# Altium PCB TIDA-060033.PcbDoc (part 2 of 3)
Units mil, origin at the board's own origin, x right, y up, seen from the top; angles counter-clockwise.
Board outline 1900 x 3360 mil, 8 copper layers (Top Layer L1, GND Plane L2, GND Plane L3, GND/Signal L4, GND Plane L5, GND Plane L6, GND Plane L7, Bottom Layer L8), stack 61.4 mil thick; 78 components, 27 nets, 146 pads, 1944 vias.
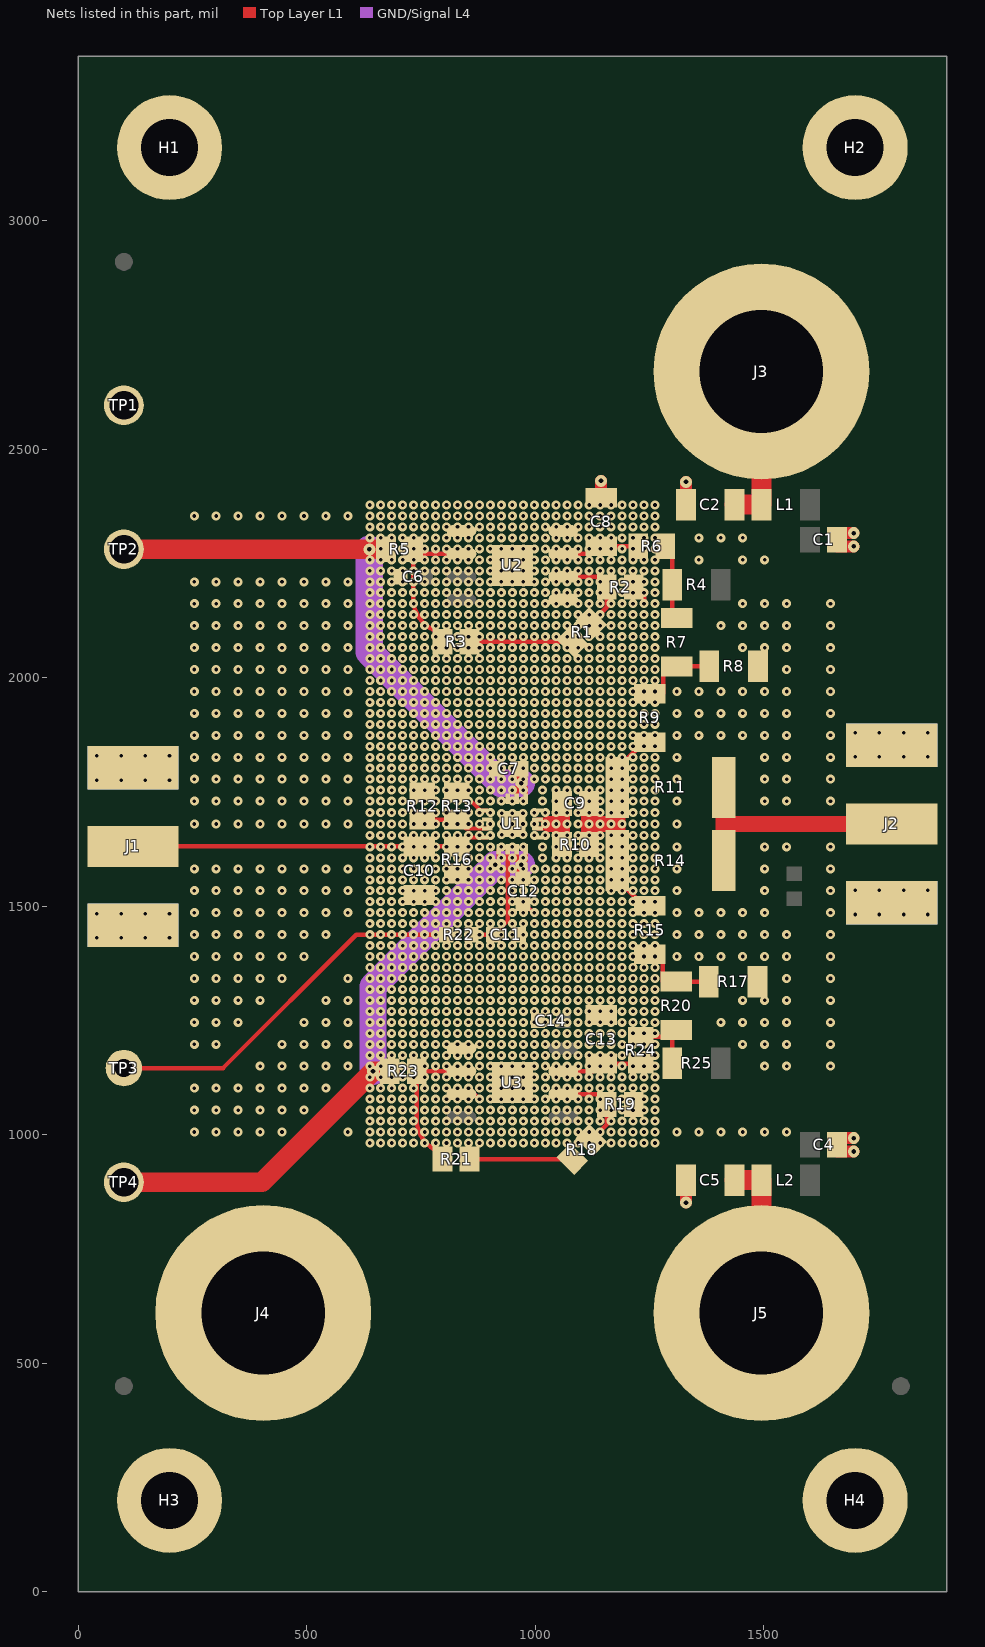
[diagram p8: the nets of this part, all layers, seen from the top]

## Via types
v1: diameter 19.68, hole 7.87, Top Layer L1 to Bottom Layer L8, tented both sides, 966 vias
v2: diameter 19.68, hole 7.87, GND Plane L5 to Bottom Layer L8, tented bottom, 941 vias
v3: diameter 19.68, hole 7.87, Top Layer L1 to Bottom Layer L8, 12 vias
v4: diameter 26, hole 10.01, Top Layer L1 to GND/Signal L4, tented both sides, 10 vias
v5: diameter 26, hole 10.01, Top Layer L1 to GND/Signal L4, tented top, 8 vias
v6: diameter 26, hole 10, Top Layer L1 to Bottom Layer L8, tented both sides, 7 vias

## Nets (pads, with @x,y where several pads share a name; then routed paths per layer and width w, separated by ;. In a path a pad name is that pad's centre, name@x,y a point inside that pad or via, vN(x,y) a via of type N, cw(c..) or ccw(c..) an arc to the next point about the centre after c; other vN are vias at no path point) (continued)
GND1: C1.2 C2.2 C4.2 C5.2 C6.2 C7.2 C8.1 C10.2 C11.2 C12.2 C13.1 C14.2 H1.1 H2.1 H3.1 H4.1 J1.2 J1.3 J1.4 J1.5 J2.2 J2.3 J2.4 J2.5 J4.1 R2.2 R8.1 R12.1 R16.1 R17.1 R19.2 TP1.1 U1.2 U1.9 U1.12 U1.15 U1.17@950,1680 U2.1 U2.4 U2.5 U2.9 U3.5 U3.7 U3.9 | length 460.8
  Top Layer L1 w9.45: C12.2@973.42,1505.07 v1(998,1486)
  Top Layer L1 w10: U3.7@838.78,1089 867,1089 v1(878,1078) ; R2.2@1215.53,2198.44 1238,2175.97 v1(1238,2162)
  Top Layer L1 w26: C8.1@1144,2393.95 v6(1144,2430.57) ; v6(1329.85,851.58) C5.2@1329.85,901 ; C2.2@1329.85,2379 v6(1329.85,2428.42) ; v6(1696.98,963.44) 1660.35,963.44 1660.35,992.56 v6(1696.98,992.56) ; v6(1696.98,2287.44) 1660.35,2287.44 1660.35,2316.56 v6(1696.98,2316.56)
  other v1: 638,982 662,982 686,982 710,982 926,982 950,982 974,982 998,982 1022,982 1214,982 1238,982 1262,982 254,1006 302,1006 350,1006 398,1006 446,1006 590,1006 638,1006 662,1006 686,1006 806,1006 830,1006 854,1006 878,1006 902,1006 926,1006 950,1006 974,1006 998,1006 1190,1006 1214,1006 1238,1006 1310,1006 1358,1006 1406,1006 1454,1006 1502,1006 1550,1006 638,1030 662,1030 686,1030 782,1030 902,1030 926,1030 950,1030 974,1030 998,1030 1214,1030 254,1054 302,1054 350,1054 398,1054 446,1054 494,1054 638,1054 662,1054 686,1054 782,1054 902,1054 926,1054 950,1054 974,1054 998,1054 638,1078 662,1078 686,1078 782,1078 902,1078 926,1078 950,1078 974,1078 998,1078 254,1102 302,1102 350,1102 398,1102 446,1102 494,1102 542,1102 878,1102 902,1102 950,1102 998,1102 902,1126 950,1126 998,1126 398,1150 446,1150 494,1150 542,1150 590,1150 902,1150 926,1150 950,1150 974,1150 998,1150 1502,1150 1550,1150 1646,1150 902,1174 926,1174 950,1174 974,1174 998,1174 254,1198 302,1198 446,1198 494,1198 542,1198 590,1198 710,1198 734,1198 758,1198 782,1198 878,1198 902,1198 926,1198 950,1198 974,1198 998,1198 1454,1198 1502,1198 1550,1198 1646,1198 710,1222 734,1222 758,1222 782,1222 806,1222 830,1222 854,1222 878,1222 902,1222 926,1222 950,1222 974,1222 998,1222 254,1246 302,1246 350,1246 494,1246 542,1246 590,1246 710,1246 734,1246 758,1246 782,1246 806,1246 830,1246 854,1246 878,1246 902,1246 926,1246 950,1246 974,1246 1406,1246 1454,1246 1502,1246 1550,1246 1646,1246 710,1270 734,1270 758,1270 782,1270 806,1270 830,1270 854,1270 878,1270 902,1270 926,1270 950,1270 974,1270 1190,1270 1214,1270 1238,1270 254,1294 302,1294 350,1294 398,1294 542,1294 590,1294 710,1294 734,1294 758,1294 782,1294 806,1294 830,1294 854,1294 878,1294 902,1294 926,1294 950,1294 974,1294 998,1294 1022,1294 1046,1294 1070,1294 1094,1294 1118,1294 1142,1294 1166,1294 1190,1294 1214,1294 1238,1294 1262,1294 1454,1294 1502,1294 1550,1294 1646,1294 710,1318 734,1318 758,1318 782,1318 806,1318 830,1318 854,1318 878,1318 902,1318 926,1318 950,1318 974,1318 998,1318 1022,1318 1046,1318 1070,1318 1094,1318 1118,1318 1142,1318 1166,1318 1190,1318 1214,1318 1238,1318 254,1342 302,1342 350,1342 398,1342 446,1342 590,1342 734,1342 758,1342 782,1342 806,1342 830,1342 854,1342 878,1342 902,1342 926,1342 950,1342 974,1342 998,1342 1022,1342 1046,1342 1070,1342 1094,1342 1118,1342 1142,1342 1166,1342 1190,1342 1214,1342 1238,1342 1550,1342 1646,1342 758,1366 782,1366 806,1366 830,1366 854,1366 878,1366 902,1366 926,1366 950,1366 974,1366 998,1366 1022,1366 1046,1366 1070,1366 1094,1366 1118,1366 1142,1366 1166,1366 1190,1366 254,1390 302,1390 350,1390 398,1390 446,1390 494,1390 782,1390 806,1390 830,1390 854,1390 878,1390 902,1390 926,1390 950,1390 974,1390 998,1390 1022,1390 1046,1390 1070,1390 1094,1390 1118,1390 1142,1390 1166,1390 1190,1390 1310,1390 1358,1390 1406,1390 1454,1390 1502,1390 1550,1390 1646,1390 998,1414 1022,1414 1046,1414 1070,1414 1094,1414 1118,1414 1142,1414 1166,1414 1190,1414 40.81,1430.97 93.81,1430.97 146.81,1430.97 199.81,1430.97 254,1438 302,1438 350,1438 398,1438 446,1438 494,1438 542,1438 998,1438 1022,1438 1046,1438 1070,1438 1094,1438 1118,1438 1142,1438 1166,1438 1190,1438 1310,1438 1358,1438 1406,1438 1454,1438 1502,1438 1550,1438 1646,1438 998,1462 1022,1462 1046,1462 1070,1462 1094,1462 1118,1462 1142,1462 1166,1462 1190,1462 1700.19,1482 1753.19,1482 1806.19,1482 1859.19,1482 40.81,1483.97 93.81,1483.97 146.81,1483.97 199.81,1483.97 254,1486 302,1486 350,1486 398,1486 446,1486 494,1486 542,1486 590,1486 638,1486 662,1486 686,1486 710,1486 878,1486 902,1486 1022,1486 1046,1486 1070,1486 1094,1486 1118,1486 1142,1486 1166,1486 1190,1486 1310,1486 1358,1486 1406,1486 1454,1486 1502,1486 1646,1486 638,1510 662,1510 686,1510 902,1510 998,1510 1022,1510 1046,1510 1070,1510 1094,1510 1118,1510 1142,1510 1166,1510 1190,1510 254,1534 302,1534 350,1534 398,1534 446,1534 494,1534 542,1534 590,1534 638,1534 662,1534 686,1534 1022,1534 1046,1534 1070,1534 1094,1534 1118,1534 1310,1534 1502,1534 1646,1534 1700.19,1535 1753.19,1535 1806.19,1535 1859.19,1535 638,1558 662,1558 686,1558 782,1558 1022,1558 1046,1558 1070,1558 1094,1558 1118,1558 1238,1558 1262,1558 254,1582 302,1582 350,1582 398,1582 446,1582 494,1582 542,1582 590,1582 638,1582 662,1582 1022,1582 1046,1582 1070,1582 1094,1582 1118,1582 1238,1582 1262,1582 1310,1582 1502,1582 1646,1582 1016,1606 1238,1606 1262,1606 1016,1630 1238,1630 1262,1630 1310,1630 1502,1630 1550,1630 1646,1630 1238,1655 1262,1655 950,1656.64 254,1680 302,1680 350,1680 398,1680 446,1680 494,1680 542,1680 590,1680 638,1680 662,1680 926.64,1680 950,1680 973.36,1680 1238,1680 1262,1680 1310,1680 950,1703.36 638,1705 662,1705 686,1705 1238,1705 1262,1705 254,1730 302,1730 350,1730 398,1730 446,1730 494,1730 542,1730 590,1730 638,1730 662,1730 686,1730 710,1730 1016,1730 1238,1730 1262,1730 1310,1730 1502,1730 1550,1730 1646,1730 638,1754 662,1754 686,1754 710,1754 1016,1754 1238,1754 1262,1754 40.81,1775.97 93.81,1775.97 146.81,1775.97 199.81,1775.97 254,1778 302,1778 350,1778 398,1778 446,1778 494,1778 542,1778 590,1778 638,1778 662,1778 686,1778 710,1778 1022,1778 1046,1778 1070,1778 1094,1778 1118,1778 1238,1778 1262,1778 1310,1778 1502,1778 1550,1778 1646,1778 638,1802 662,1802 686,1802 710,1802 734,1802 758,1802 782,1802 806,1802 1022,1802 1046,1802 1070,1802 1094,1802 1118,1802 1238,1802 1262,1802 254,1826 302,1826 350,1826 398,1826 446,1826 494,1826 542,1826 590,1826 638,1826 662,1826 686,1826 710,1826 734,1826 758,1826 782,1826 1022,1826 1046,1826 1070,1826 1094,1826 1118,1826 1310,1826 1502,1826 1550,1826 1646,1826 1700.19,1827 1753.19,1827 1806.19,1827 1859.19,1827 40.81,1828.97 93.81,1828.97 146.81,1828.97 199.81,1828.97 638,1850 662,1850 686,1850 710,1850 734,1850 758,1850 926,1850 950,1850 974,1850 998,1850 1022,1850 1046,1850 1070,1850 1094,1850 1118,1850 1142,1850 1166,1850 1190,1850 254,1874 302,1874 350,1874 398,1874 446,1874 494,1874 542,1874 590,1874 638,1874 662,1874 686,1874 710,1874 734,1874 902,1874 926,1874 950,1874 974,1874 998,1874 1022,1874 1046,1874 1070,1874 1094,1874 1118,1874 1142,1874 1166,1874 1190,1874 1310,1874 1358,1874 1406,1874 1454,1874 1502,1874 1550,1874 1646,1874 1700.19,1880 1753.19,1880 1806.19,1880 1859.19,1880 638,1898 662,1898 686,1898 710,1898 878,1898 902,1898 926,1898 950,1898 974,1898 998,1898 1022,1898 1046,1898 1070,1898 1094,1898 1118,1898 1142,1898 1166,1898 1190,1898 254,1922 302,1922 350,1922 398,1922 446,1922 494,1922 542,1922 590,1922 638,1922 662,1922 686,1922 854,1922 878,1922 902,1922 926,1922 950,1922 974,1922 998,1922 1022,1922 1046,1922 1070,1922 1094,1922 1118,1922 1142,1922 1166,1922 1190,1922 1214,1922 1238,1922 1262,1922 1310,1922 1358,1922 1406,1922 1454,1922 1502,1922 1550,1922 1646,1922 638,1946 662,1946 830,1946 854,1946 878,1946 902,1946 926,1946 950,1946 974,1946 998,1946 1022,1946 1046,1946 1070,1946 1094,1946 1118,1946 1142,1946 1166,1946 1190,1946 254,1970 302,1970 350,1970 398,1970 446,1970 494,1970 542,1970 590,1970 638,1970 806,1970 830,1970 854,1970 878,1970 902,1970 926,1970 950,1970 974,1970 998,1970 1022,1970 1046,1970 1070,1970 1094,1970 1118,1970 1142,1970 1166,1970 1190,1970 1310,1970 1358,1970 1406,1970 1454,1970 1502,1970 1550,1970 1646,1970 782,1994 806,1994 830,1994 854,1994 878,1994 902,1994 926,1994 950,1994 974,1994 998,1994 1022,1994 1046,1994 1070,1994 1094,1994 1118,1994 1142,1994 1166,1994 1190,1994 254,2018 302,2018 350,2018 398,2018 446,2018 494,2018 542,2018 590,2018 758,2018 782,2018 806,2018 830,2018 854,2018 878,2018 902,2018 926,2018 950,2018 974,2018 998,2018 1022,2018 1046,2018 1118,2018 1142,2018 1166,2018 1190,2018 1214,2018 1238,2018 1550,2018 1646,2018 734,2042 926,2042 950,2042 974,2042 998,2042 1022,2042 1142,2042 1166,2042 1190,2042 1214,2042 1238,2042 254,2066 302,2066 350,2066 398,2066 446,2066 494,2066 542,2066 590,2066 710,2066 734,2066 1166,2066 1190,2066 1214,2066 1238,2066 1262,2066 1454,2066 1502,2066 1550,2066 1646,2066 686,2090 710,2090 734,2090 1190,2090 1214,2090 1238,2090 254,2114 302,2114 350,2114 398,2114 446,2114 494,2114 542,2114 590,2114 686,2114 710,2114 926,2114 950,2114 974,2114 998,2114 1022,2114 1214,2114 1238,2114 1406,2114 1454,2114 1502,2114 1550,2114 1646,2114 686,2138 806,2138 830,2138 854,2138 878,2138 902,2138 926,2138 950,2138 974,2138 998,2138 1022,2138 1046,2138 1190,2138 1214,2138 1238,2138 254,2162 302,2162 350,2162 398,2162 446,2162 494,2162 542,2162 590,2162 686,2162 782,2162 902,2162 926,2162 950,2162 974,2162 998,2162 1022,2162 1454,2162 1502,2162 1550,2162 1646,2162 686,2186 902,2186 926,2186 950,2186 974,2186 998,2186 254,2210 302,2210 350,2210 398,2210 446,2210 494,2210 542,2210 590,2210 902,2210 926,2210 950,2210 974,2210 998,2210 902,2234 950,2234 998,2234 902,2258 950,2258 998,2258 1358,2258 1454,2258 1502,2258 902,2282 926,2282 950,2282 974,2282 998,2282 902,2306 926,2306 950,2306 974,2306 998,2306 1358,2306 1406,2306 1454,2306 878,2330 902,2330 926,2330 950,2330 974,2330 998,2330 1022,2330 254,2354 302,2354 350,2354 398,2354 446,2354 494,2354 542,2354 590,2354 638,2354 662,2354 686,2354 710,2354 734,2354 638,2378 662,2378 686,2378 710,2378 734,2378 758,2378
  other v2: 734,982 758,982 782,982 806,982 830,982 854,982 878,982 902,982 1046,982 1070,982 1094,982 1118,982 1142,982 1166,982 1190,982 710,1006 734,1006 758,1006 782,1006 1022,1006 1046,1006 1070,1006 1094,1006 1118,1006 1142,1006 1166,1006 1262,1006 710,1030 734,1030 758,1030 806,1030 830,1030 854,1030 878,1030 1022,1030 1046,1030 1070,1030 1094,1030 1118,1030 1142,1030 1166,1030 1190,1030 1238,1030 1262,1030 710,1054 734,1054 758,1054 806,1054 830,1054 854,1054 878,1054 1022,1054 1046,1054 1070,1054 1094,1054 1118,1054 1142,1054 1166,1054 1190,1054 1214,1054 1238,1054 1262,1054 710,1078 734,1078 758,1078 806,1078 830,1078 854,1078 1022,1078 1046,1078 1070,1078 1094,1078 1118,1078 1142,1078 1166,1078 1190,1078 1214,1078 1238,1078 1262,1078 638,1102 662,1102 686,1102 710,1102 734,1102 758,1102 782,1102 806,1102 830,1102 854,1102 1022,1102 1046,1102 1070,1102 1094,1102 1118,1102 1142,1102 1166,1102 1190,1102 1214,1102 1238,1102 1262,1102 638,1126 662,1126 686,1126 710,1126 734,1126 758,1126 782,1126 806,1126 830,1126 854,1126 878,1126 1022,1126 1046,1126 1070,1126 1094,1126 1118,1126 1142,1126 1166,1126 1190,1126 1214,1126 1238,1126 1262,1126 638,1150 662,1150 686,1150 710,1150 734,1150 758,1150 782,1150 806,1150 830,1150 854,1150 878,1150 1022,1150 1046,1150 1070,1150 1094,1150 1118,1150 1142,1150 1166,1150 1190,1150 1214,1150 1238,1150 1262,1150 638,1174 662,1174 686,1174 710,1174 734,1174 758,1174 782,1174 806,1174 830,1174 854,1174 878,1174 1022,1174 1046,1174 1070,1174 1094,1174 1118,1174 1142,1174 1166,1174 1190,1174 1214,1174 1238,1174 1262,1174 638,1198 662,1198 686,1198 806,1198 830,1198 854,1198 1022,1198 1046,1198 1070,1198 1094,1198 1118,1198 1142,1198 1166,1198 1190,1198 1214,1198 1238,1198 1262,1198 638,1222 662,1222 686,1222 1022,1222 1046,1222 1070,1222 1094,1222 1118,1222 1142,1222 1166,1222 1190,1222 1214,1222 1238,1222 1262,1222 638,1246 662,1246 686,1246 998,1246 1022,1246 1046,1246 1070,1246 1094,1246 1118,1246 1142,1246 1166,1246 1190,1246 1214,1246 1238,1246 1262,1246 638,1270 662,1270 686,1270 998,1270 1022,1270 1046,1270 1070,1270 1094,1270 1118,1270 1142,1270 1166,1270 1262,1270 638,1294 662,1294 686,1294 638,1318 662,1318 686,1318 1262,1318 638,1342 662,1342 686,1342 710,1342 1262,1342 638,1366 662,1366 686,1366 710,1366 734,1366 1214,1366 1238,1366 1262,1366 638,1390 662,1390 686,1390 710,1390 734,1390 758,1390 1214,1390 1238,1390 1262,1390 638,1414 662,1414 686,1414 710,1414 734,1414 758,1414 782,1414 806,1414 830,1414 854,1414 878,1414 902,1414 926,1414 950,1414 974,1414 1214,1414 1238,1414 1262,1414 638,1438 662,1438 686,1438 710,1438 734,1438 758,1438 782,1438 806,1438 830,1438 854,1438 878,1438 902,1438 926,1438 950,1438 974,1438 1214,1438 1238,1438 1262,1438 638,1462 662,1462 686,1462 710,1462 734,1462 758,1462 782,1462 806,1462 830,1462 854,1462 878,1462 902,1462 926,1462 950,1462 974,1462 1214,1462 1238,1462 1262,1462 734,1486 758,1486 782,1486 806,1486 830,1486 854,1486 926,1486 950,1486 974,1486 1214,1486 1238,1486 1262,1486 710,1510 734,1510 758,1510 782,1510 806,1510 830,1510 854,1510 878,1510 926,1510 950,1510 974,1510 1214,1510 1238,1510 1262,1510 710,1534 734,1534 758,1534 782,1534 806,1534 830,1534 854,1534 878,1534 902,1534 926,1534 950,1534 974,1534 998,1534 1142,1534 1166,1534 1190,1534 1214,1534 1238,1534 1262,1534 710,1558 734,1558 758,1558 806,1558 830,1558 854,1558 878,1558 902,1558 926,1558 950,1558 974,1558 998,1558 1142,1558 1166,1558 1190,1558 1214,1558 686,1582 710,1582 734,1582 758,1582 782,1582 806,1582 830,1582 854,1582 878,1582 902,1582 926,1582 950,1582 974,1582 998,1582 1142,1582 1166,1582 1190,1582 1214,1582 638,1606 662,1606 686,1606 710,1606 734,1606 758,1606 782,1606 806,1606 830,1606 854,1606 878,1606 902,1606 926,1606 950,1606 974,1606 1046,1606 1070,1606 1094,1606 1118,1606 1142,1606 1166,1606 1190,1606 1214,1606 638,1630 662,1630 686,1630 710,1630 734,1630 758,1630 782,1630 806,1630 830,1630 854,1630 878,1630 902,1630 926,1630 950,1630 974,1630 1046,1630 1070,1630 1094,1630 1118,1630 1142,1630 1166,1630 1190,1630 1214,1630 638,1655 662,1655 686,1655 710,1655 734,1655 758,1655 782,1655 806,1655 830,1655 854,1655 878,1655 902,1655 998,1655 1022,1655 1046,1655 1070,1655 1094,1655 1118,1655 1142,1655 1166,1655 1190,1655 1214,1655 686,1680 710,1680 734,1680 758,1680 782,1680 806,1680 830,1680 854,1680 878,1680 902,1680 998,1680 1022,1680 1046,1680 1070,1680 1094,1680 1118,1680 1142,1680 1166,1680 1190,1680 1214,1680 710,1705 734,1705 758,1705 782,1705 806,1705 830,1705 854,1705 878,1705 902,1705 998,1705 1022,1705 1046,1705 1070,1705 1094,1705 1118,1705 1142,1705 1166,1705 1190,1705 1214,1705 734,1730 758,1730 782,1730 806,1730 830,1730 854,1730 878,1730 902,1730 926,1730 950,1730 974,1730 1046,1730 1070,1730 1094,1730 1118,1730 1142,1730 1166,1730 1190,1730 1214,1730 734,1754 758,1754 782,1754 806,1754 830,1754 854,1754 878,1754 902,1754 926,1754 950,1754 974,1754 1046,1754 1070,1754 1094,1754 1118,1754 1142,1754 1166,1754 1190,1754 1214,1754 734,1778 758,1778 782,1778 806,1778 830,1778 854,1778 878,1778 902,1778 926,1778 950,1778 974,1778 998,1778 1142,1778 1166,1778 1190,1778 1214,1778 830,1802 854,1802 878,1802 902,1802 926,1802 950,1802 974,1802 998,1802 1142,1802 1166,1802 1190,1802 1214,1802 806,1826 830,1826 854,1826 878,1826 902,1826 926,1826 950,1826 974,1826 998,1826 1142,1826 1166,1826 1190,1826 1214,1826 1238,1826 1262,1826 782,1850 806,1850 830,1850 854,1850 878,1850 902,1850 1214,1850 1238,1850 1262,1850 758,1874 782,1874 806,1874 830,1874 854,1874 878,1874 1214,1874 1238,1874 1262,1874 734,1898 758,1898 782,1898 806,1898 830,1898 854,1898 1214,1898 1238,1898 1262,1898 710,1922 734,1922 758,1922 782,1922 806,1922 830,1922 686,1946 710,1946 734,1946 758,1946 782,1946 806,1946 1214,1946 1238,1946 1262,1946 662,1970 686,1970 710,1970 734,1970 758,1970 782,1970 1214,1970 1238,1970 1262,1970 638,1994 662,1994 686,1994 710,1994 734,1994 758,1994 1214,1994 1238,1994 1262,1994 638,2018 662,2018 686,2018 710,2018 734,2018 1070,2018 1094,2018 1262,2018 638,2042 662,2042 686,2042 710,2042 758,2042 782,2042 806,2042 830,2042 854,2042 878,2042 902,2042 1046,2042 1070,2042 1094,2042 1118,2042 1262,2042 638,2066 662,2066 686,2066 758,2066 782,2066 806,2066 830,2066 854,2066 878,2066 902,2066 926,2066 950,2066 974,2066 998,2066 1022,2066 1046,2066 1070,2066 1094,2066 1118,2066 1142,2066 638,2090 662,2090 758,2090 782,2090 806,2090 830,2090 854,2090 878,2090 902,2090 926,2090 950,2090 974,2090 998,2090 1022,2090 1046,2090 1070,2090 1094,2090 1118,2090 1142,2090 1166,2090 1262,2090 638,2114 662,2114 734,2114 758,2114 782,2114 806,2114 830,2114 854,2114 878,2114 902,2114 1046,2114 1070,2114 1094,2114 1118,2114 1142,2114 1166,2114 1190,2114 1262,2114 638,2138 662,2138 710,2138 734,2138 758,2138 782,2138 1070,2138 1094,2138 1118,2138 1142,2138 1166,2138 1262,2138 638,2162 662,2162 710,2162 734,2162 758,2162 806,2162 830,2162 854,2162 878,2162 1046,2162 1070,2162 1094,2162 1118,2162 1142,2162 1166,2162 1190,2162 1214,2162 1262,2162 638,2186 662,2186 710,2186 734,2186 758,2186 782,2186 806,2186 830,2186 854,2186 878,2186 1022,2186 1046,2186 1070,2186 1094,2186 1118,2186 1142,2186 1166,2186 1190,2186 1214,2186 1238,2186 1262,2186 638,2210 662,2210 686,2210 710,2210 734,2210 758,2210 782,2210 806,2210 830,2210 854,2210 878,2210 1022,2210 1046,2210 1070,2210 1094,2210 1118,2210 1142,2210 1166,2210 1190,2210 1214,2210 1238,2210 1262,2210 638,2234 662,2234 686,2234 710,2234 734,2234 758,2234 782,2234 806,2234 830,2234 854,2234 878,2234 1022,2234 1046,2234 1070,2234 1094,2234 1118,2234 1142,2234 1166,2234 1190,2234 1214,2234 1238,2234 1262,2234 638,2258 662,2258 686,2258 710,2258 734,2258 758,2258 782,2258 806,2258 830,2258 854,2258 878,2258 1022,2258 1046,2258 1070,2258 1094,2258 1118,2258 1142,2258 1166,2258 1190,2258 1214,2258 1238,2258 1262,2258 638,2282 662,2282 686,2282 710,2282 734,2282 758,2282 782,2282 806,2282 830,2282 854,2282 878,2282 1022,2282 1046,2282 1070,2282 1094,2282 1118,2282 1142,2282 1166,2282 1190,2282 1214,2282 1238,2282 1262,2282 638,2306 662,2306 686,2306 710,2306 734,2306 758,2306 782,2306 806,2306 830,2306 854,2306 878,2306 1022,2306 1046,2306 1070,2306 1094,2306 1118,2306 1142,2306 1166,2306 1190,2306 1214,2306 1238,2306 1262,2306 638,2330 662,2330 686,2330 710,2330 734,2330 758,2330 782,2330 806,2330 830,2330 854,2330 1046,2330 1070,2330 1094,2330 1118,2330 1142,2330 1166,2330 1190,2330 1214,2330 1238,2330 1262,2330 758,2354 782,2354 806,2354 830,2354 854,2354 878,2354 902,2354 926,2354 950,2354 974,2354 998,2354 1022,2354 1046,2354 1070,2354 1094,2354 1118,2354 1142,2354 1166,2354 1190,2354 1214,2354 1238,2354 1262,2354 782,2378 806,2378 830,2378 854,2378 878,2378 902,2378 926,2378 950,2378 974,2378 998,2378 1022,2378 1046,2378 1070,2378 1094,2378 1118,2378 1142,2378 1166,2378 1190,2378 1214,2378 1238,2378 1262,2378
  other v3: 926,1102 974,1102 926,1126 974,1126 926.64,1656.64 973.36,1656.64 926.64,1703.36 973.36,1703.36 926,2234 974,2234 926,2258 974,2258
NetC2_1: C2.1 J3.1 L1.1 | length 349.8
  Top Layer L1 w43.31: C2.1@1436.15,2379 L1.1@1495,2379 J3.1@1495,2670
NetC5_1: C5.1 J5.1 L2.1 | length 349.8
  Top Layer L1 w43.31: C5.1@1436.15,901 L2.1@1495,901 J5.1@1495,610
NetC7_1: C7.1 R5.1 TP2.1 U1.13 U1.14 | length 1357.7
  Top Layer L1 w9.45: U1.14@959.84,1735.12 959.84,1759.25 v5(969.69,1769.09) 979.53,1759.25 U1.13@979.53,1735.12
  Top Layer L1 w26: v5(969.69,1769.09) C7.1@969.69,1800.79
  Top Layer L1 w43.31: TP2.1@100,2281 v5(637.13,2281) R5.1@673.75,2281
  GND/Signal L4 w60: v5(637.13,2281) 637.13,2056.37 924.41,1769.09 v5(969.69,1769.09)
NetC8_2: C8.2 R6.2 U2.3 | length 171.1
  Top Layer L1 w10: U2.3@1061.22,2271 1127.35,2271 C8.2@1144,2287.65 R6.2@1225.47,2287.65
NetC9_1: C9.1 R10.2 U1.10 U1.11 | length 176.4
  Top Layer L1 w9.45: U1.10@1005.12,1670.16 1020.09,1670.16 1029.93,1680 1020.09,1689.84 U1.11@1005.12,1689.84
  Top Layer L1 w35: 1029.93,1680 1058.47,1680 ; R10.2@1058.47,1634.94 1058.47,1680 ; C9.1@1058.47,1725.06 1058.47,1680
NetC9_2: C9.2 R9.1 R10.1 R11.2 R14.2 R15.2 | length 584.5
  Top Layer L1 w10: R14.2@1179.86,1600.09 1179.86,1559.14 1237.85,1501.15 R15.2@1251,1501.15 ; R11.2@1179.86,1759.91 1179.86,1800.86 1237.85,1858.85 R9.1@1251,1858.85
  Top Layer L1 w35: R10.1@1117.53,1634.94 C9.2@1117.53,1725.06 ; 1117.53,1680 1179.86,1680 ; R14.2@1179.86,1600.09 R11.2@1179.86,1759.91
NetC10_1: C10.1 J1.1 R16.2 U1.4 | length 783
  Top Layer L1 w9.45: R16.2@828.5,1630.97 848,1650.47 U1.4@894.88,1650.47
  Top Layer L1 w10: J1.1@120,1630.97 R16.2@828.5,1630.97
NetC11_1: C11.1 R22.2 U1.6 | length 248.5
  Top Layer L1 w9.45: C11.1@908.46,1437.41 940.16,1469.11 U1.6@940.16,1624.88
  Top Layer L1 w10: R22.2@860.56,1437.41 C11.1@908.46,1437.41
NetC12_1: C12.1 R23.1 TP4.1 U1.5 U1.7 U1.8 | length 1448.1
  Top Layer L1 w9.45: v5(912.2,1590.91) 920.47,1599.18 U1.5@920.47,1624.88 ; U1.7@959.84,1624.88 959.84,1600.75 v5(969.69,1590.91) 979.53,1600.75 U1.8@979.53,1624.88
  Top Layer L1 w26: v5(969.69,1590.91) 969.68,1563.92 C12.1@973.42,1560.19
  Top Layer L1 w43.31: TP4.1@100,896 402.01,896 v5(645.01,1139) R23.1@681.63,1139
  GND/Signal L4 w60: v5(645.01,1139) 645.01,1323.72 v5(912.2,1590.91) v5(969.69,1590.91)
NetC13_2: C13.2 R24.2 U3.3 | length 176.7
  Top Layer L1 w10: U3.3@1061.22,1139 1127.35,1139 C13.2@1144,1155.65 R24.2@1231,1155.65
NetJ2_1: J2.1 R11.1 R14.1 | length 527.7
  Top Layer L1 w35: R14.1@1412.14,1600.09 R11.1@1412.14,1759.91 ; 1412.14,1680 J2.1@1780,1680
NetR1_1: R1.1 R3.1 | length 224.5
  Top Layer L1 w10: R3.1@856.31,2078.89 R1.1@1080.81,2078.88
NetR1_2: R1.2 R2.1 U2.2 | length 196.4
  Top Layer L1 w10: U2.2@1061.22,2221 1133.91,2221 R2.1@1156.47,2198.44 1156.47,2154.54 R1.2@1122.57,2120.64
NetR3_2: R3.2 R5.2 U2.6 | length 308
  Top Layer L1 w10: R3.2@794.78,2099.85 cw(c807.81,2173.71) 732.81,2173.47 732.81,2271 U2.6@838.78,2271
NetR4_1: R4.1 R6.1 R7.2 | length 163
  Top Layer L1 w10: R6.1@1284.53,2287.65 1299.85,2272.33 R4.1@1299.85,2204 R7.2@1299.85,2131
NetR7_1: R7.1 R8.2 R9.2 | length 190.3
  Top Layer L1 w10: R9.2@1264.15,1965.15 R9.2@1251,1965.15 1280.45,1965.15 1280.45,2024.7 R7.1@1309.9,2024.7 ; R7.1@1322.15,2024.7 R8.2@1380.85,2024.7
NetR12_2: R12.2 R13.1 U1.3 | length 150
  Top Layer L1 w9.45: R13.1@828.5,1689.66 848,1670.16 U1.3@894.88,1670.16
  Top Layer L1 w10: R12.2@753,1689.66 R13.1@828.5,1689.66
NetR13_2: R13.2 U1.1 | length 82.6
  Top Layer L1 w9.45: R13.2@828.5,1748.71 841.09,1748.71 880.27,1709.53 U1.1@894.88,1709.53
NetR15_1: R15.1 R17.2 R20.2 | length 201.6
  Top Layer L1 w10: R15.1@1264.15,1394.85 R15.1@1251,1394.85 1279.4,1394.85 1279.4,1335.3 R20.2@1308.85,1335.3 R17.2@1379.85,1335.3
NetR18_1: R18.1 R21.1 | length 224.5
  Top Layer L1 w10: R21.1@856.31,946.89 R18.1@1080.81,946.88
NetR18_2: R18.2 R19.1 U3.2 | length 196.4
  Top Layer L1 w10: U3.2@1061.22,1089 1133.91,1089 R19.1@1156.47,1066.44 1156.47,1022.54 R18.2@1122.57,988.64
NetR20_1: R20.1 R24.1 R25.2 | length 150.9
  Top Layer L1 w10: R24.1@1231,1214.71 1308.85,1214.71 R20.1@1308.85,1229 ; R25.2@1299.85,1156 R20.1@1299.85,1214.71
NetR21_2: R21.2 R23.2 U3.6 | length 308.1
  Top Layer L1 w10: 740.69,1031.47 R23.2@740.69,1137 ; 740.69,1033.47 ccw(c815.69,1033.71) R21.2@802.66,959.85 ; R23.2@740.69,1139 U3.6@838.78,1139
NetR22_1: R22.1 TP3.1 | length 826.1
  Top Layer L1 w10: TP3.1@100,1146 317,1146 608.41,1437.41 757.54,1437.41 R22.1@805.44,1437.41
pads on no net: FID1.1 FID2.1 FID3.1 FID4.1 FID5.1 FID6.1 LBL1.0 U1.16 U1.17@950,1680 U2.8 U3.8

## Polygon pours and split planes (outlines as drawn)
GND1 on Top Layer L1 "Top Layer L1-GND1" (solid, remove dead copper, pour order 18): 20,20 1880,20 1880,3340 20,3340
NetR21_2 on Top Layer L1 "Top Layer L1-NetR28_2" (solid, pour order 0): 762.88,1167 719,1167 719,1111 762.88,1111 785.84,1133.96 785.84,1144.04
NetR3_2 on Top Layer L1 "Top Layer L1-NetR38_2" (solid, pour order 2): 745.12,2309 711.12,2309 711.12,2253 765,2253 777.96,2265.96 777.96,2276.16
GND1 on Bottom Layer L8 "Bottom Layer L8-GND1" (solid, remove dead copper, pour order 30): 20,20 1880,20 1880,3340 20,3340
GND1 on GND/Signal L4 "GND?Signal L4-GND1" (solid, remove dead copper, pour order 28): 20,20 1880,20 1880,3340 20,3340
GND1 on GND Plane L2 (split plane): 1879.9,20.1 20.1,20.1 20.1,1577.97 228,1577.97 228,1617.72 703.66,1617.72 703.66,1601.32 864.06,1601.32 864.06,1637.5 904.71,1637.55 908.6,1638.33 911.91,1640.53 914.11,1643.84 914.89,1647.73 914.89,1653.21 914.11,1657.11 911.97,1660.32 914.11,1663.52 914.89,1667.42 914.89,1672.9 914.11,1676.79 911.91,1680.1 908.6,1682.3 904.71,1683.08 864.06,1683.13 864.06,1700.86 868.68,1702.77 871.1,1700.35 875.31,1697.54 880.27,1696.55 904.71,1696.61 908.6,1697.38 911.91,1699.59 914.11,1702.89 914.89,1706.79 914.89,1712.27 914.11,1716.16 911.91,1719.47 908.6,1721.67 904.71,1722.45 885.65,1722.5 864.06,1744.09 864.06,1778.37 792.94,1778.37 792.94,1720.8 788.56,1719.31 717.44,1719.31 717.44,1660.63 703.66,1660.63 703.66,1644.23 228,1644.23 228,1683.97 20.1,1683.97 20.1,3339.9 1879.9,3339.9
GND1 on GND Plane L3 (split plane): 1879.9,20.1 20.1,20.1 20.1,1577.97 228,1577.97 228,1617.72 703.66,1617.72 703.66,1601.32 864.06,1601.32 864.06,1637.5 904.71,1637.55 908.6,1638.33 911.91,1640.53 914.11,1643.84 914.89,1647.73 914.89,1653.21 914.11,1657.11 911.97,1660.32 914.11,1663.52 914.89,1667.42 914.89,1672.9 914.11,1676.79 911.91,1680.1 908.6,1682.3 904.71,1683.08 864.06,1683.13 864.06,1700.86 868.68,1702.77 871.1,1700.35 875.31,1697.54 880.27,1696.55 904.71,1696.61 908.6,1697.38 911.91,1699.59 914.11,1702.89 914.89,1706.79 914.89,1712.27 914.11,1716.16 911.91,1719.47 908.6,1721.67 904.71,1722.45 885.65,1722.5 864.06,1744.09 864.06,1778.37 792.94,1778.37 792.94,1720.8 788.56,1719.31 717.44,1719.31 717.44,1660.63 703.66,1660.63 703.66,1644.23 228,1644.23 228,1683.97 20.1,1683.97 20.1,3339.9 1879.9,3339.9
GND1 on GND Plane L5 (split plane): 1879.9,20.1 20.1,20.1 20.1,3339.9 1879.9,3339.9
GND1 on GND Plane L6 (split plane): 1879.9,20.1 20.1,20.1 20.1,3339.9 1879.9,3339.9
GND1 on GND Plane L7 (split plane): 1879.9,20.1 20.1,20.1 20.1,3339.9 1879.9,3339.9

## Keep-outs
Keep-Out Layer:
  text ".Layer_Name" at 577,-858.49 h60

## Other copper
Top Layer L1:
  text ".Layer_Name" at 577,-858.49 h60
GND/Signal L4:
  pour cut-out: 1267.45,1995.05 1267.45,2054.35 1351.2,2054.35 1351.2,2067.15 1410.5,2067.15 1410.5,1983.4 1351.2,1983.4 1351.2,1995.05 1293.45,1995.05 1293.45,1935.5 1208.55,1935.5 1208.55,1995.05
  pour cut-out: 1195.44,1244.36 1195.44,1185.06 1270.2,1185.06 1270.2,1113.55 1329.5,1113.55 1329.5,1199.35 1351.3,1199.35 1351.3,1258.65 1266.56,1258.65 1266.56,1244.36
  pour cut-out: 1254.87,2323.21 1314.18,2323.21 1314.18,2252.09 1313.11,2252.09 1313.11,2246.45 1329.5,2246.45 1329.5,2160.65 1352.35,2160.65 1352.35,2101.35 1267.45,2101.35 1267.45,2160.65 1270.2,2160.65 1270.2,2246.45 1286.6,2246.45 1286.6,2252.09 1254.87,2252.09
  pour cut-out: 0,1577.97 228,1577.97 228,1617.72 703.66,1617.72 703.66,1601.32 864.06,1601.32 864.06,1637.5 904.71,1637.55 908.6,1638.33 911.91,1640.53 914.11,1643.84 914.89,1647.73 914.89,1653.21 914.11,1657.11 911.97,1660.32 914.11,1663.52 914.89,1667.42 914.89,1672.9 914.11,1676.79 911.91,1680.1 908.6,1682.3 904.71,1683.08 864.06,1683.13 864.06,1700.86 868.68,1702.77 871.1,1700.35 875.31,1697.54 880.27,1696.55 904.71,1696.61 908.6,1697.38 911.91,1699.59 914.11,1702.89 914.89,1706.79 914.89,1712.27 914.11,1716.16 911.91,1719.47 908.6,1721.67 904.71,1722.45 885.65,1722.5 864.06,1744.09 864.06,1778.37 792.94,1778.37 792.94,1720.8 788.56,1719.31 717.44,1719.31 717.44,1660.63 703.66,1660.63 703.66,1644.23 228,1644.23 228,1683.97 0,1683.97
  pour cut-out: 1028.82,1599.38 1087.21,1599.38 1087.21,1760.62 1028.82,1760.62 1028.82,1705.78 1019.98,1704.02 1018.18,1702.82 1005.12,1702.82 995.29,1702.76 991.4,1701.99 988.09,1699.78 985.89,1696.48 985.36,1693.81 985.11,1692.58 985.11,1687.1 985.89,1683.21 988.03,1680 985.89,1676.79 985.11,1672.9 985.11,1667.42 985.89,1663.52 988.03,1660.32 991.4,1658.01 995.29,1657.24 1004.85,1657.24 1018.18,1657.18 1019.98,1655.98 1028.82,1654.22
  pour cut-out: 1186.13,1102 1186.13,1030.88 1169.73,1030.88 1169.73,1022.54 1168.72,1017.47 1165.03,1012.35 1152.91,1000.24 1168.68,984.47 1084.99,900.77 1052.13,933.63 885.97,933.63 885.97,911.33 767.6,911.33 767.6,959.63 766.56,960.19 753.16,971.19 742.16,984.59 733.99,999.87 728.96,1016.46 727.71,1029.14 727.29,1033.42 727.43,1102.84 719,1102.84 715.99,1103.44 711.03,1103.44 711.03,1174.56 716,1174.56 719,1175.16 762.88,1175.16 765.88,1174.56 770.34,1174.56 770.34,1171.07 789.16,1152.25 802.94,1152.25 804.1,1153.99 810.98,1158.59 819.09,1160.2 858.46,1160.2 866.58,1158.59 873.46,1153.99 878.05,1147.11 879.67,1139 878.05,1130.89 873.46,1124.01 866.58,1119.41 858.46,1117.8 819.09,1117.8 810.98,1119.41 804.1,1124.01 802.94,1125.75 789.16,1125.75 770.34,1106.93 770.34,1103.44 765.89,1103.44 762.88,1102.84 753.94,1102.84 753.94,1033.18 755.08,1021.66 758.59,1010.06 764.3,999.38 769.54,993 771.99,990.01 781.21,982.44 885.97,982.44 885.97,960.14 1043.78,960.14 1118.4,1034.76 1121.82,1031.33 1126.82,1033.4 1126.82,1075.75 1097.06,1075.75 1095.9,1074.01 1089.02,1069.41 1080.91,1067.8 1041.54,1067.8 1033.42,1069.41 1026.54,1074.01 1021.95,1080.89 1020.33,1089 1021.95,1097.11 1026.54,1103.99 1033.42,1108.59 1041.54,1110.2 1080.91,1110.2 1089.02,1108.59 1095.9,1103.99 1097.06,1102.25
  pour cut-out: 1186.13,1102 1186.13,1030.88 1169.73,1030.88 1169.73,1022.54 1168.72,1017.47 1165.03,1012.35 1152.91,1000.24 1168.68,984.47 1084.99,900.77 1052.13,933.63 885.97,933.63 885.97,911.33 767.6,911.33 767.6,959.63 766.56,960.19 753.16,971.19 742.16,984.59 733.99,999.87 728.96,1016.46 727.71,1029.14 727.29,1033.42 727.43,1102.84 719,1102.84 715.99,1103.44 711.03,1103.44 711.03,1174.56 716,1174.56 719,1175.16 762.88,1175.16 765.88,1174.56 770.34,1174.56 770.34,1171.07 789.16,1152.25 802.94,1152.25 804.1,1153.99 810.98,1158.59 819.09,1160.2 858.46,1160.2 866.58,1158.59 873.46,1153.99 878.05,1147.11 879.67,1139 878.05,1130.89 873.46,1124.01 866.58,1119.41 858.46,1117.8 819.09,1117.8 810.98,1119.41 804.1,1124.01 802.94,1125.75 789.16,1125.75 770.34,1106.93 770.34,1103.44 765.89,1103.44 762.88,1102.84 753.94,1102.84 753.94,1033.18 755.08,1021.66 758.59,1010.06 764.3,999.38 769.54,993 771.99,990.01 781.21,982.44 885.97,982.44 885.97,960.14 1043.78,960.14 1118.4,1034.76 1121.82,1031.33 1126.82,1033.4 1126.82,1075.75 1097.06,1075.75 1095.9,1074.01 1089.02,1069.41 1080.91,1067.8 1041.54,1067.8 1033.42,1069.41 1026.54,1074.01 1021.95,1080.89 1020.33,1089 1021.95,1097.11 1026.54,1103.99 1033.42,1108.59 1041.54,1110.2 1080.91,1110.2 1089.02,1108.59 1095.9,1103.99 1097.06,1102.25
  pour cut-out: 1186.13,2234 1186.13,2162.88 1169.73,2162.88 1169.73,2154.54 1168.72,2149.47 1165.84,2145.17 1152.91,2132.24 1168.68,2116.47 1084.99,2032.77 1052.13,2065.63 885.97,2065.63 885.97,2043.33 767.6,2043.33 767.6,2095.42 758.68,2100.19 745.28,2111.19 734.28,2124.59 726.11,2139.87 721.08,2156.46 719.52,2173.42 719.55,2244.84 711.12,2244.84 708.12,2245.44 703.15,2245.44 703.15,2316.56 708.12,2316.56 711.12,2317.16 745.12,2317.16 748.12,2316.56 762.46,2316.56 762.46,2303.19 781.4,2284.25 802.94,2284.25 804.1,2285.99 810.98,2290.59 819.1,2292.2 858.46,2292.2 866.58,2290.59 873.46,2285.99 878.05,2279.11 879.67,2271 878.05,2262.89 873.46,2256.01 866.58,2251.41 858.46,2249.8 819.1,2249.8 810.98,2251.41 804.1,2256.01 802.94,2257.75 781.28,2257.75 770.77,2247.23 768.12,2245.46 765,2244.84 746.06,2244.84 746.06,2173.47 747.2,2161.66 750.71,2150.06 756.42,2139.38 764.11,2130.01 773.47,2122.33 784.16,2116.62 791.33,2114.44 885.97,2114.44 885.97,2092.14 1043.78,2092.14 1118.4,2166.76 1121.82,2163.33 1126.82,2165.4 1126.82,2207.75 1097.06,2207.75 1095.9,2206.01 1089.02,2201.41 1080.91,2199.8 1041.54,2199.8 1033.42,2201.41 1026.54,2206.01 1021.95,2212.89 1020.33,2221 1021.95,2229.11 1026.54,2235.99 1033.42,2240.59 1041.54,2242.2 1080.91,2242.2 1089.02,2240.59 1095.9,2235.99 1097.06,2234.25
  pour cut-out: 1350.2,1292.85 1409.5,1292.85 1409.5,1377.75 1350.2,1377.75 1350.2,1364.95 1293.45,1364.95 1293.45,1424.5 1208.55,1424.5 1208.55,1365.2 1266.4,1365.2 1266.4,1305.65 1350.2,1305.65
  text ".Layer_Name" at 577,-858.49 h60
Bottom Layer L8:
  region net GND1: 1660,2390 240,2390 240,970 1660,970
  text ".Layer_Name" at 577,-858.49 h60
GND Plane L2 (plane layer: these items are gaps in the copper):
  pour cut-out: 1254.87,2323.21 1314.18,2323.21 1314.18,2252.09 1313.11,2252.09 1313.11,2246.45 1329.5,2246.45 1329.5,2160.65 1352.35,2160.65 1352.35,2101.35 1267.45,2101.35 1267.45,2160.65 1270.2,2160.65 1270.2,2246.45 1286.6,2246.45 1286.6,2252.09 1254.87,2252.09
  pour cut-out: 1267.45,1995.05 1267.45,2054.35 1351.2,2054.35 1351.2,2067.15 1410.5,2067.15 1410.5,1983.4 1351.2,1983.4 1351.2,1995.05 1293.45,1995.05 1293.45,1935.5 1208.55,1935.5 1208.55,1995.05
  pour cut-out: 1028.82,1599.38 1087.21,1599.38 1087.21,1760.62 1028.82,1760.62 1028.82,1705.78 1019.98,1704.02 1018.18,1702.82 1005.12,1702.82 995.29,1702.76 991.4,1701.99 988.09,1699.78 985.89,1696.48 985.36,1693.81 985.11,1692.58 985.11,1687.1 985.89,1683.21 988.03,1680 985.89,1676.79 985.11,1672.9 985.11,1667.42 985.89,1663.52 988.03,1660.32 991.4,1658.01 995.29,1657.24 1004.85,1657.24 1018.18,1657.18 1019.98,1655.98 1028.82,1654.22
  pour cut-out: 0,1577.97 228,1577.97 228,1617.72 703.66,1617.72 703.66,1601.32 864.06,1601.32 864.06,1637.5 904.71,1637.55 908.6,1638.33 911.91,1640.53 914.11,1643.84 914.89,1647.73 914.89,1653.21 914.11,1657.11 911.97,1660.32 914.11,1663.52 914.89,1667.42 914.89,1672.9 914.11,1676.79 911.91,1680.1 908.6,1682.3 904.71,1683.08 864.06,1683.13 864.06,1700.86 868.68,1702.77 871.1,1700.35 875.31,1697.54 880.27,1696.55 904.71,1696.61 908.6,1697.38 911.91,1699.59 914.11,1702.89 914.89,1706.79 914.89,1712.27 914.11,1716.16 911.91,1719.47 908.6,1721.67 904.71,1722.45 885.65,1722.5 864.06,1744.09 864.06,1778.37 792.94,1778.37 792.94,1720.8 788.56,1719.31 717.44,1719.31 717.44,1660.63 703.66,1660.63 703.66,1644.23 228,1644.23 228,1683.97 0,1683.97
  pour cut-out: 1186.13,1102 1186.13,1030.88 1169.73,1030.88 1169.73,1022.54 1168.72,1017.47 1165.03,1012.35 1152.91,1000.24 1168.68,984.47 1084.99,900.77 1052.13,933.63 885.97,933.63 885.97,911.33 767.6,911.33 767.6,959.63 766.56,960.19 753.16,971.19 742.16,984.59 733.99,999.87 728.96,1016.46 727.71,1029.14 727.29,1033.42 727.43,1102.84 719,1102.84 715.99,1103.44 711.03,1103.44 711.03,1174.56 716,1174.56 719,1175.16 762.88,1175.16 765.88,1174.56 770.34,1174.56 770.34,1171.07 789.16,1152.25 802.94,1152.25 804.1,1153.99 810.98,1158.59 819.09,1160.2 858.46,1160.2 866.58,1158.59 873.46,1153.99 878.05,1147.11 879.67,1139 878.05,1130.89 873.46,1124.01 866.58,1119.41 858.46,1117.8 819.09,1117.8 810.98,1119.41 804.1,1124.01 802.94,1125.75 789.16,1125.75 770.34,1106.93 770.34,1103.44 765.89,1103.44 762.88,1102.84 753.94,1102.84 753.94,1033.18 755.08,1021.66 758.59,1010.06 764.3,999.38 769.54,993 771.99,990.01 781.21,982.44 885.97,982.44 885.97,960.14 1043.78,960.14 1118.4,1034.76 1121.82,1031.33 1126.82,1033.4 1126.82,1075.75 1097.06,1075.75 1095.9,1074.01 1089.02,1069.41 1080.91,1067.8 1041.54,1067.8 1033.42,1069.41 1026.54,1074.01 1021.95,1080.89 1020.33,1089 1021.95,1097.11 1026.54,1103.99 1033.42,1108.59 1041.54,1110.2 1080.91,1110.2 1089.02,1108.59 1095.9,1103.99 1097.06,1102.25
  pour cut-out: 1186.13,2234 1186.13,2162.88 1169.73,2162.88 1169.73,2154.54 1168.72,2149.47 1165.84,2145.17 1152.91,2132.24 1168.68,2116.47 1084.99,2032.77 1052.13,2065.63 885.97,2065.63 885.97,2043.33 767.6,2043.33 767.6,2095.42 758.68,2100.19 745.28,2111.19 734.28,2124.59 726.11,2139.87 721.08,2156.46 719.52,2173.42 719.55,2244.84 711.12,2244.84 708.12,2245.44 703.15,2245.44 703.15,2316.56 708.12,2316.56 711.12,2317.16 745.12,2317.16 748.12,2316.56 762.46,2316.56 762.46,2303.19 781.4,2284.25 802.94,2284.25 804.1,2285.99 810.98,2290.59 819.1,2292.2 858.46,2292.2 866.58,2290.59 873.46,2285.99 878.05,2279.11 879.67,2271 878.05,2262.89 873.46,2256.01 866.58,2251.41 858.46,2249.8 819.1,2249.8 810.98,2251.41 804.1,2256.01 802.94,2257.75 781.28,2257.75 770.77,2247.23 768.12,2245.46 765,2244.84 746.06,2244.84 746.06,2173.47 747.2,2161.66 750.71,2150.06 756.42,2139.38 764.11,2130.01 773.47,2122.33 784.16,2116.62 791.33,2114.44 885.97,2114.44 885.97,2092.14 1043.78,2092.14 1118.4,2166.76 1121.82,2163.33 1126.82,2165.4 1126.82,2207.75 1097.06,2207.75 1095.9,2206.01 1089.02,2201.41 1080.91,2199.8 1041.54,2199.8 1033.42,2201.41 1026.54,2206.01 1021.95,2212.89 1020.33,2221 1021.95,2229.11 1026.54,2235.99 1033.42,2240.59 1041.54,2242.2 1080.91,2242.2 1089.02,2240.59 1095.9,2235.99 1097.06,2234.25
  pour cut-out: 1350.2,1292.85 1409.5,1292.85 1409.5,1377.75 1350.2,1377.75 1350.2,1364.95 1293.45,1364.95 1293.45,1424.5 1208.55,1424.5 1208.55,1365.2 1266.4,1365.2 1266.4,1305.65 1350.2,1305.65
  pour cut-out: 1195.44,1244.36 1195.44,1185.06 1270.2,1185.06 1270.2,1113.55 1329.5,1113.55 1329.5,1199.35 1351.3,1199.35 1351.3,1258.65 1266.56,1258.65 1266.56,1244.36
  lines w40: 0,0 1900,0
  text ".Layer_Name" at 577,-858.49 h60
GND Plane L7 (plane layer: these items are gaps in the copper):
  lines w40: 0,0 1900,0
  text ".Layer_Name" at 577,-858.49 h60
GND Plane L3 (plane layer: these items are gaps in the copper):
  pour cut-out: 1254.87,2323.21 1314.18,2323.21 1314.18,2252.09 1313.11,2252.09 1313.11,2246.45 1329.5,2246.45 1329.5,2160.65 1352.35,2160.65 1352.35,2101.35 1267.45,2101.35 1267.45,2160.65 1270.2,2160.65 1270.2,2246.45 1286.6,2246.45 1286.6,2252.09 1254.87,2252.09
  pour cut-out: 1267.45,1995.05 1267.45,2054.35 1351.2,2054.35 1351.2,2067.15 1410.5,2067.15 1410.5,1983.4 1351.2,1983.4 1351.2,1995.05 1293.45,1995.05 1293.45,1935.5 1208.55,1935.5 1208.55,1995.05
  pour cut-out: 1028.82,1599.38 1087.21,1599.38 1087.21,1760.62 1028.82,1760.62 1028.82,1705.78 1019.98,1704.02 1018.18,1702.82 1005.12,1702.82 995.29,1702.76 991.4,1701.99 988.09,1699.78 985.89,1696.48 985.36,1693.81 985.11,1692.58 985.11,1687.1 985.89,1683.21 988.03,1680 985.89,1676.79 985.11,1672.9 985.11,1667.42 985.89,1663.52 988.03,1660.32 991.4,1658.01 995.29,1657.24 1004.85,1657.24 1018.18,1657.18 1019.98,1655.98 1028.82,1654.22
  pour cut-out: 0,1577.97 228,1577.97 228,1617.72 703.66,1617.72 703.66,1601.32 864.06,1601.32 864.06,1637.5 904.71,1637.55 908.6,1638.33 911.91,1640.53 914.11,1643.84 914.89,1647.73 914.89,1653.21 914.11,1657.11 911.97,1660.32 914.11,1663.52 914.89,1667.42 914.89,1672.9 914.11,1676.79 911.91,1680.1 908.6,1682.3 904.71,1683.08 864.06,1683.13 864.06,1700.86 868.68,1702.77 871.1,1700.35 875.31,1697.54 880.27,1696.55 904.71,1696.61 908.6,1697.38 911.91,1699.59 914.11,1702.89 914.89,1706.79 914.89,1712.27 914.11,1716.16 911.91,1719.47 908.6,1721.67 904.71,1722.45 885.65,1722.5 864.06,1744.09 864.06,1778.37 792.94,1778.37 792.94,1720.8 788.56,1719.31 717.44,1719.31 717.44,1660.63 703.66,1660.63 703.66,1644.23 228,1644.23 228,1683.97 0,1683.97
  pour cut-out: 1186.13,1102 1186.13,1030.88 1169.73,1030.88 1169.73,1022.54 1168.72,1017.47 1165.03,1012.35 1152.91,1000.24 1168.68,984.47 1084.99,900.77 1052.13,933.63 885.97,933.63 885.97,911.33 767.6,911.33 767.6,959.63 766.56,960.19 753.16,971.19 742.16,984.59 733.99,999.87 728.96,1016.46 727.71,1029.14 727.29,1033.42 727.43,1102.84 719,1102.84 715.99,1103.44 711.03,1103.44 711.03,1174.56 716,1174.56 719,1175.16 762.88,1175.16 765.88,1174.56 770.34,1174.56 770.34,1171.07 789.16,1152.25 802.94,1152.25 804.1,1153.99 810.98,1158.59 819.09,1160.2 858.46,1160.2 866.58,1158.59 873.46,1153.99 878.05,1147.11 879.67,1139 878.05,1130.89 873.46,1124.01 866.58,1119.41 858.46,1117.8 819.09,1117.8 810.98,1119.41 804.1,1124.01 802.94,1125.75 789.16,1125.75 770.34,1106.93 770.34,1103.44 765.89,1103.44 762.88,1102.84 753.94,1102.84 753.94,1033.18 755.08,1021.66 758.59,1010.06 764.3,999.38 769.54,993 771.99,990.01 781.21,982.44 885.97,982.44 885.97,960.14 1043.78,960.14 1118.4,1034.76 1121.82,1031.33 1126.82,1033.4 1126.82,1075.75 1097.06,1075.75 1095.9,1074.01 1089.02,1069.41 1080.91,1067.8 1041.54,1067.8 1033.42,1069.41 1026.54,1074.01 1021.95,1080.89 1020.33,1089 1021.95,1097.11 1026.54,1103.99 1033.42,1108.59 1041.54,1110.2 1080.91,1110.2 1089.02,1108.59 1095.9,1103.99 1097.06,1102.25
  pour cut-out: 1186.13,1102 1186.13,1030.88 1169.73,1030.88 1169.73,1022.54 1168.72,1017.47 1165.03,1012.35 1152.91,1000.24 1168.68,984.47 1084.99,900.77 1052.13,933.63 885.97,933.63 885.97,911.33 767.6,911.33 767.6,959.63 766.56,960.19 753.16,971.19 742.16,984.59 733.99,999.87 728.96,1016.46 727.71,1029.14 727.29,1033.42 727.43,1102.84 719,1102.84 715.99,1103.44 711.03,1103.44 711.03,1174.56 716,1174.56 719,1175.16 762.88,1175.16 765.88,1174.56 770.34,1174.56 770.34,1171.07 789.16,1152.25 802.94,1152.25 804.1,1153.99 810.98,1158.59 819.09,1160.2 858.46,1160.2 866.58,1158.59 873.46,1153.99 878.05,1147.11 879.67,1139 878.05,1130.89 873.46,1124.01 866.58,1119.41 858.46,1117.8 819.09,1117.8 810.98,1119.41 804.1,1124.01 802.94,1125.75 789.16,1125.75 770.34,1106.93 770.34,1103.44 765.89,1103.44 762.88,1102.84 753.94,1102.84 753.94,1033.18 755.08,1021.66 758.59,1010.06 764.3,999.38 769.54,993 771.99,990.01 781.21,982.44 885.97,982.44 885.97,960.14 1043.78,960.14 1118.4,1034.76 1121.82,1031.33 1126.82,1033.4 1126.82,1075.75 1097.06,1075.75 1095.9,1074.01 1089.02,1069.41 1080.91,1067.8 1041.54,1067.8 1033.42,1069.41 1026.54,1074.01 1021.95,1080.89 1020.33,1089 1021.95,1097.11 1026.54,1103.99 1033.42,1108.59 1041.54,1110.2 1080.91,1110.2 1089.02,1108.59 1095.9,1103.99 1097.06,1102.25
  pour cut-out: 1186.13,2234 1186.13,2162.88 1169.73,2162.88 1169.73,2154.54 1168.72,2149.47 1165.84,2145.17 1152.91,2132.24 1168.68,2116.47 1084.99,2032.77 1052.13,2065.63 885.97,2065.63 885.97,2043.33 767.6,2043.33 767.6,2095.42 758.68,2100.19 745.28,2111.19 734.28,2124.59 726.11,2139.87 721.08,2156.46 719.52,2173.42 719.55,2244.84 711.12,2244.84 708.12,2245.44 703.15,2245.44 703.15,2316.56 708.12,2316.56 711.12,2317.16 745.12,2317.16 748.12,2316.56 762.46,2316.56 762.46,2303.19 781.4,2284.25 802.94,2284.25 804.1,2285.99 810.98,2290.59 819.1,2292.2 858.46,2292.2 866.58,2290.59 873.46,2285.99 878.05,2279.11 879.67,2271 878.05,2262.89 873.46,2256.01 866.58,2251.41 858.46,2249.8 819.1,2249.8 810.98,2251.41 804.1,2256.01 802.94,2257.75 781.28,2257.75 770.77,2247.23 768.12,2245.46 765,2244.84 746.06,2244.84 746.06,2173.47 747.2,2161.66 750.71,2150.06 756.42,2139.38 764.11,2130.01 773.47,2122.33 784.16,2116.62 791.33,2114.44 885.97,2114.44 885.97,2092.14 1043.78,2092.14 1118.4,2166.76 1121.82,2163.33 1126.82,2165.4 1126.82,2207.75 1097.06,2207.75 1095.9,2206.01 1089.02,2201.41 1080.91,2199.8 1041.54,2199.8 1033.42,2201.41 1026.54,2206.01 1021.95,2212.89 1020.33,2221 1021.95,2229.11 1026.54,2235.99 1033.42,2240.59 1041.54,2242.2 1080.91,2242.2 1089.02,2240.59 1095.9,2235.99 1097.06,2234.25
  pour cut-out: 1350.2,1292.85 1409.5,1292.85 1409.5,1377.75 1350.2,1377.75 1350.2,1364.95 1293.45,1364.95 1293.45,1424.5 1208.55,1424.5 1208.55,1365.2 1266.4,1365.2 1266.4,1305.65 1350.2,1305.65
  pour cut-out: 1195.44,1244.36 1195.44,1185.06 1270.2,1185.06 1270.2,1113.55 1329.5,1113.55 1329.5,1199.35 1351.3,1199.35 1351.3,1258.65 1266.56,1258.65 1266.56,1244.36
  lines w40: 0,0 1900,0
  text ".Layer_Name" at 577,-858.49 h60
GND Plane L5 (plane layer: these items are gaps in the copper):
  lines w40: 0,0 1900,0
  text ".Layer_Name" at 577,-858.49 h60
GND Plane L6 (plane layer: these items are gaps in the copper):
  lines w40: 0,0 1900,0
  text ".Layer_Name" at 577,-858.49 h60

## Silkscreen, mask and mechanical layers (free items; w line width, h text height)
Top Overlay:
  text ".Layer_Name" at 577,-858.49 h60
Bottom Overlay:
  text ".Layer_Name" at 577,-858.49 h60
Top Paste:
  text ".Layer_Name" at 577,-858.49 h60
Bottom Paste:
  text ".Layer_Name" at 577,-858.49 h60
Top Solder:
  text ".Layer_Name" at 577,-858.49 h60
  text ".Layer_Name" at 577,-858.49 h60
Bottom Solder:
  region: 1660,2390 240,2390 240,970 1660,970
  text ".Layer_Name" at 577,-858.49 h60
Drill Guide:
  text ".Layer_Name" at 577,-858.49 h60
M1 Board Outline:
  the board outline again, w10
  text ".Layer_Name" at 577,-858.49 h60
M2 Board Dimensions:
  rectangle: 125,-400 500,-275
  rectangle: 0,-275 125,-150
  lines w7: 0,-275 1000,-275 ; 125,-400 125,-150 ; 250,-400 250,-150 ; 500,-400 500,-150 ; 750,-400 750,-150 ; 0,-400 0,-150 1000,-150 1000,-400 0,-400
  text ".Layer_Name" at 577,-858.49 h60
M3 3D STEP Top:
  text ".Layer_Name" at 577,-858.49 h60
M4 3D STEP Bottom:
  text ".Layer_Name" at 577,-858.49 h60
M5 Assembly Top:
  lines w10: -292,-930.17 6308,-930.17 ; -292,-726.83 6310,-726.83 ; -292,-523.5 -292,-1133.5 3713,-1133.5 6310,-1133.5 6310,-523.5 -291.5,-523.5 -291.5,-1133.5 1284,-1133.5 ; 2173,-1133.5 2173,-523.5 ; 3440,-726.83 3440,-523.5 ; 4280,-726.83 4280,-523.5 ; 4902,-1140 4902,-937.17
  text "COMPONENTS MARKED 'DNP' SHOULD NOT BE POPULATED." at 1153.5,-318.5 h60
  text "ASSEMBLY VARIANT:" at 1153,-434 h60
  text ".VariantName" at 2189,-434 h60
  text "PCB VIEWED FROM TOP SIDE" at -228.5,-655.67 h60
  text "BOARD #:" at 2248,-655.67 h60
  text ".PRJ_Number" at 2793.5,-655.67 h60
  text "REV:" at 3638,-655.67 h60
  text ".PCB_Rev" at 3929.5,-655.67 h60
  text "SVN REV:" at 4476,-655.67 h60
  text ".VersionControl_RevNumber" at 4982,-655.67 h60
  text "TID #:" at 2248,-859 h60
  text ".TID" at 2793.5,-859 h60
  text "PLOT NAME =" at -228.5,-1064.34 h60
  text ".plot_File_Name" at 577,-1064.34 h60
  text "GENERATED    :" at 2250,-1064.34 h60
  text ".Print_Date" at 3119.5,-1064.34 h60
  text ".Print_Time" at 3848.5,-1064.34 h60
  text "TEXAS INSTRUMENTS" at 5113,-1064.34 h60
M6 Assembly Bottom:
  lines w10: -292.5,-727.33 6309.5,-727.33 ; -290.5,-930.67 6309.5,-930.67 ; 1115.5,-1140.5 1115.5,-937.67 ; 1737.5,-727.33 1737.5,-524 ; 2577.5,-727.33 2577.5,-524 ; 3844.5,-1134 3844.5,-524 ; 4733.5,-1134 6309,-1134 6309,-524 -292.5,-524 -292.5,-1134 2304.5,-1134 6309.5,-1134 6309.5,-524
  text "COMPONENTS MARKED 'DNP' SHOULD NOT BE POPULATED." at 6102,-318 h60
  text ".VariantName" at 5058,-434 h60
  text "ASSEMBLY VARIANT:" at 6097,-434 h60
  text ".VersionControl_RevNumber" at 1035.5,-656.17 h60
  text "SVN REV:" at 1541.5,-656.17 h60
  text ".PCB_Rev" at 2088,-656.17 h60
  text "REV:" at 2379.5,-656.17 h60
  text ".PRJ_Number" at 3224,-656.17 h60
  text "BOARD #:" at 3769.5,-656.17 h60
  text "PCB VIEWED FROM BOTTOM SIDE" at 6246,-656.17 h60
  text ".TID" at 3224,-859.5 h60
  text "TID #:" at 3769.5,-859.5 h60
  text "TEXAS INSTRUMENTS" at 904.5,-1064.84 h60
  text ".Print_Time" at 2169,-1064.84 h60
  text ".Print_Date" at 2898,-1064.84 h60
  text "GENERATED    :" at 3767.5,-1064.84 h60
  text ".plot_File_Name" at 5440.5,-1064.84 h60
  text "PLOT NAME =" at 6246,-1064.84 h60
